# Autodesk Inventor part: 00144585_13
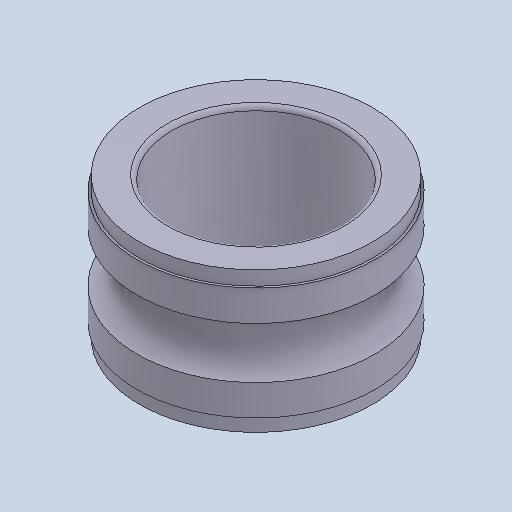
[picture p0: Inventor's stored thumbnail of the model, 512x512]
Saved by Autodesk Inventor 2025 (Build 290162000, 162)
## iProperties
Created: 2021-02
Part Number: 00144585_13
Material: Generico
Document SubType Name: Modeling
Designer: Ryzen5700u
Density: 1 g/cm^3
Appearance: Default
Author: Ryzen5700u
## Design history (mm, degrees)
feature "Solido1"
node "Solido2"
